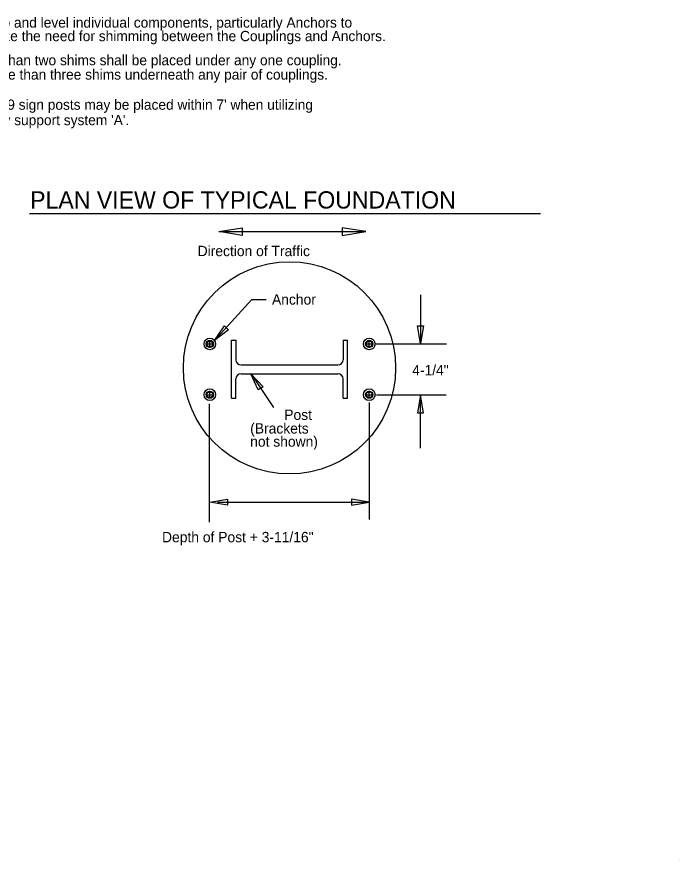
# Model space of a CAD drawing. Extents: x 12.3 to 19.6, y 5.8 to 16.1.
# Drawn here: x 15.752 to 19.621, y 5.937 to 10.858 of the extents above; entities that cross this region are included whole.
import ezdxf

# ---------------------------------------------------------------- set-up
doc = ezdxf.new("R2010")
doc.units = 0
for name, color, linetype in [('DETL-DIMS', 7, 'Continuous'), ('DETL-LINE', 7, 'Continuous'), ('DETL-NOTE', 7, 'Continuous'), ('TTLB-TEXT', 7, 'Continuous')]:
    doc.layers.add(name, color=color, linetype=linetype)

msp = doc.modelspace()

# ---------------------------------------------------------------- linework, layer by layer
at = {"layer": 'DEFPOINTS'}
for p, q in [((18.1098, 8.6508), (18.1098, 8.6508)), ((16.8794, 8.0231), (16.8794, 8.0231))]:
    msp.add_line(p, q, dxfattribs=at)
at = {"layer": 'DETL-DIMS'}
for p, q in [((16.9319, 9.6036), (17.7905, 9.6036)), ((17.1254, 9.2062), (16.9062, 8.9679)), ((17.1254, 9.2062), (17.209, 9.2062)), ((18.1098, 9.2331), (18.1098, 8.9495)), ((17.852, 8.9471), (18.2613, 8.9471)), ((17.253, 8.5752), (17.1201, 8.7737)), ((17.8539, 8.6508), (18.2604, 8.6508)), ((18.1098, 8.3387), (18.1098, 8.6498)), ((16.8764, 8.5964), (16.8764, 7.9052)), ((17.8108, 8.6048), (17.8108, 7.9211)), ((16.9251, 8.0231), (17.8108, 8.0231))]:
    msp.add_line(p, q, dxfattribs=at)
for points in [[(17.069, 9.6264), (17.069, 9.5807), (16.9319, 9.6036)], [(17.6533, 9.6264), (17.6533, 9.5807), (17.7905, 9.6036)], [(16.9643, 9.0538), (16.9894, 9.0304), (16.9067, 8.9669)], [(18.0927, 9.0524), (18.127, 9.0524), (18.1098, 8.9495)], [(17.1902, 8.6972), (17.1616, 8.6782), (17.1191, 8.7735)], [(18.0927, 8.5445), (18.127, 8.5445), (18.1098, 8.6474)], [(16.9823, 8.0402), (16.9823, 8.0059), (16.8794, 8.0231)], [(17.7079, 8.0402), (17.7079, 8.0059), (17.8108, 8.0231)]]:
    msp.add_lwpolyline(points, close=True, dxfattribs=at)
at = {"layer": 'DETL-LINE'}
for p, q in [((16.8794, 8.9242), (16.8794, 8.97)), ((17.0064, 8.6296), (17.0064, 8.9683)), ((17.0064, 8.9683), (17.0318, 8.9683)), ((17.0318, 8.9683), (17.0318, 8.8546)), ((17.6584, 8.9683), (17.6838, 8.9683)), ((17.6584, 8.9683), (17.6584, 8.8546)), ((17.6838, 8.6296), (17.6838, 8.9683)), ((17.8108, 8.9242), (17.8108, 8.97)), ((16.8565, 8.9471), (16.9022, 8.9471)), ((17.7879, 8.9471), (17.8336, 8.9471)), ((17.8108, 8.9471), (17.8108, 8.9471)), ((17.062, 8.8243), (17.6281, 8.8243)), ((17.062, 8.7735), (17.6281, 8.7735)), ((17.0318, 8.6296), (17.0318, 8.7433)), ((17.6584, 8.6296), (17.6584, 8.7433)), ((16.8794, 8.6279), (16.8794, 8.6736)), ((17.8108, 8.6279), (17.8108, 8.6736)), ((16.8565, 8.6508), (16.9022, 8.6508)), ((16.8794, 8.6508), (16.8794, 8.6508)), ((17.0064, 8.6296), (17.0318, 8.6296)), ((17.6584, 8.6296), (17.6838, 8.6296)), ((17.7879, 8.6508), (17.8336, 8.6508)), ((17.8108, 8.6508), (17.8108, 8.6508)), ((17.8108, 8.6508), (17.8108, 8.6508))]:
    msp.add_line(p, q, dxfattribs=at)
for centre, radius in [((17.3451, 8.8075), 0.62), ((16.8794, 8.9471), 0.0339), ((16.8794, 8.9471), 0.0212), ((16.8794, 8.9471), 0.0169), ((17.8108, 8.9471), 0.0339), ((17.8108, 8.9471), 0.0212), ((17.8108, 8.9471), 0.0169), ((16.8794, 8.6508), 0.0339), ((16.8794, 8.6508), 0.0212), ((16.8794, 8.6508), 0.0169), ((17.8108, 8.6508), 0.0339), ((17.8108, 8.6508), 0.0212), ((17.8108, 8.6508), 0.0169)]:
    msp.add_circle(centre, radius, dxfattribs=at)
for centre, start, end in [((17.062, 8.8546), 180, 270), ((17.6281, 8.8546), 270, 0), ((17.062, 8.7433), 90, 180), ((17.6281, 8.7433), 0, 90)]:
    msp.add_arc(centre, 0.0302, start, end, dxfattribs=at)
at = {"layer": 'DETL-NOTE'}
msp.add_line((15.8256, 9.7087), (18.8123, 9.7087), dxfattribs=at)
at = {"layer": 'TTLB-TEXT'}
msp.add_line((19.6215, 5.9375), (19.6215, 5.9375), dxfattribs=at)

# ---------------------------------------------------------------- texts
at = {"layer": 'DETL-NOTE'}
for s, height, p in [('5. Square-up and level individual components, particularly Anchors to', 0.06, (15.2488, 10.7948)), ('minimize the need for shimming between the Couplings and Anchors.', 0.06, (15.4413, 10.7159)), ('6. No more than two shims shall be placed under any one coupling.', 0.06, (15.2591, 10.5751)), ('No more than three shims underneath any pair of couplings.', 0.06, (15.4375, 10.4911)), ("7. Two W6X9 sign posts may be placed within 7' when utilizing", 0.06, (15.2591, 10.3152)), ("   breakaway support system 'A'.", 0.06, (15.2591, 10.2252)), ('PLAN VIEW OF TYPICAL FOUNDATION', 0.1008, (15.8296, 9.7383)), ('Direction of Traffic', 0.06048, (16.8082, 9.46)), ('Anchor', 0.06048, (17.2427, 9.1771)), ('4-1/4"', 0.06048, (18.0618, 8.7637)), ('Post', 0.06048, (17.3145, 8.5032)), ('(Brackets', 0.06048, (17.1153, 8.4238)), ('not shown)', 0.06048, (17.1153, 8.3469)), ('Depth of Post + 3-11/16"', 0.06048, (16.6004, 7.7887))]:
    msp.add_text(s, height=height, dxfattribs=at).set_placement(p)

doc.saveas('drawing.dxf')
